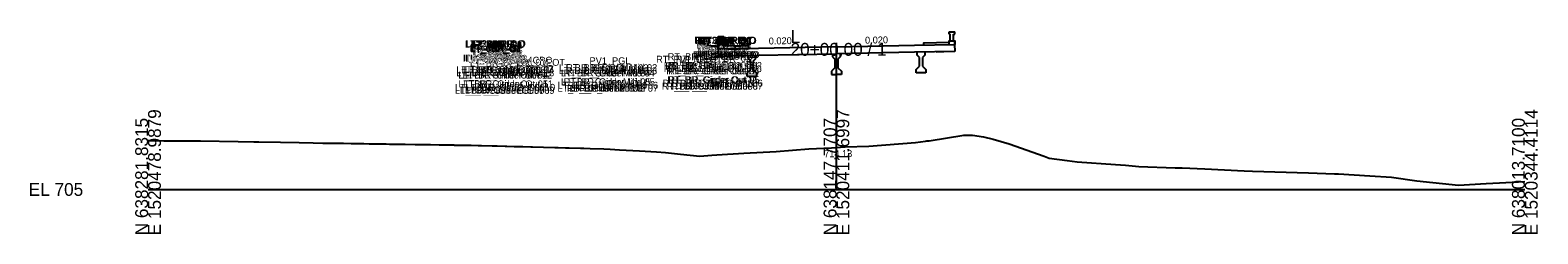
# Model space of a CAD drawing. Extents: x -26 to 3903, y -10 to 9531.
# Drawn here: x 974.3 to 1302.8, y -9.7 to 34.8 of the extents above; entities that cross this region are included whole.
import ezdxf

# ---------------------------------------------------------------- set-up
doc = ezdxf.new("R2010")
doc.units = 0
for name, color, linetype in [('Default', 7, 'Continuous'), ('Exist Cross Section Cell', 7, 'Continuous'), ('Exist XS Center Line Elevation Label', 7, 'Continuous'), ('Exist XS Ground Line', 7, 'Continuous'), ('Prop CMT Conc Surface', 7, 'Continuous'), ('Prop XS Conc Monolithic Island', 7, 'Continuous'), ('Prop XS Finish Grade', 7, 'Continuous'), ('Prop XS SE Text', 7, 'Continuous')]:
    doc.layers.add(name, color=color, linetype=linetype)

msp = doc.modelspace()

# ---------------------------------------------------------------- linework, layer by layer
at = {"layer": 'Exist Cross Section Cell'}
for p, q in [((1150, 0), (1150, 31.96)), ((1000, 0), (1150, 0)), ((1150, 0), (1300, 0))]:
    msp.add_line(p, q, dxfattribs=at)
at = {"layer": 'Exist XS Ground Line'}
msp.add_lwpolyline([(1000, 10.65), (1001.54, 10.65), (1003.43, 10.64), (1008.98, 10.64), (1011.39, 10.63), (1019.6, 10.46), (1023.06, 10.38), (1024.11, 10.36), (1028.84, 10.28), (1032.95, 10.21), (1035.98, 10.16), (1038.09, 10.13), (1038.91, 10.12), (1039.29, 10.11), (1040.73, 10.1), (1041.42, 10.09), (1042.61, 10.07), (1044.23, 10.04), (1044.45, 10.04), (1044.85, 10.03), (1046.3, 10.01), (1047.03, 10), (1048.17, 9.98), (1049.82, 9.96), (1050.46, 9.95), (1051.89, 9.92), (1052.61, 9.91), (1054.79, 9.88), (1055.41, 9.87), (1056.02, 9.86), (1058.21, 9.82), (1060.48, 9.79), (1061.01, 9.79), (1061.18, 9.78), (1061.54, 9.78), (1063.42, 9.75), (1063.8, 9.74), (1064.51, 9.74), (1065.79, 9.72), (1066.61, 9.7), (1066.77, 9.69), (1067.09, 9.69), (1068.33, 9.69), (1068.63, 9.68), (1070.37, 9.63), (1071.95, 9.59), (1072.35, 9.58), (1072.66, 9.57), (1075, 9.51), (1076.07, 9.49), (1077.8, 9.44), (1077.94, 9.44), (1078.21, 9.43), (1079.8, 9.4), (1080.59, 9.38), (1081.66, 9.35), (1083.4, 9.31), (1083.52, 9.31), (1083.77, 9.3), (1086.19, 9.24), (1088.61, 9.18), (1088.98, 9.17), (1089.1, 9.17), (1089.35, 9.16), (1090.97, 9.11), (1091.78, 9.09), (1094.22, 9.02), (1094.57, 9.01), (1094.69, 9), (1094.92, 9), (1096.37, 8.94), (1099.35, 8.87), (1100.7, 8.78), (1102.72, 8.65), (1107.06, 8.4), (1110.79, 8.18), (1112.74, 8.07), (1116.05, 7.73), (1120.24, 7.26), (1122.82, 7.5), (1123.92, 7.58), (1129.85, 7.93), (1136.85, 8.28), (1143.98, 8.85), (1148.9, 9.07), (1151.92, 9.27), (1157.06, 9.44), (1167.22, 10.27), (1169.41, 10.55), (1169.69, 10.6), (1169.85, 10.62), (1170.17, 10.62), (1177.79, 11.86), (1179.64, 11.83), (1182.08, 11.46), (1184.16, 10.99), (1187.66, 9.95), (1195.23, 7.28), (1195.97, 6.98), (1196.38, 6.84), (1200.26, 6.35), (1202.47, 6.05), (1210.8, 5.46), (1213.02, 5.3), (1215.89, 5.03), (1223.78, 4.75), (1225.37, 4.69), (1230.31, 4.48), (1238.84, 4.09), (1240.68, 4), (1252.88, 3.62), (1258.54, 3.43), (1259.39, 3.38), (1266.2, 2.98), (1270.96, 2.66), (1276.48, 1.89), (1285.57, 0.9), (1291.6, 1.29), (1294.51, 1.46), (1300, 1.76)], dxfattribs=at)
at = {"layer": 'Prop XS Conc Monolithic Island'}
for p, q in [((1124.22, 32.85), (1124.22, 33.35)), ((1124.22, 33.35), (1125.47, 33.35)), ((1125.47, 32.85), (1125.47, 33.35)), ((1174.53, 33.88), (1174.53, 34.38)), ((1174.53, 34.38), (1175.78, 34.38)), ((1174.78, 33.88), (1174.53, 33.88)), ((1174.78, 32.38), (1174.78, 33.88)), ((1175.53, 32.38), (1175.53, 33.88)), ((1175.53, 33.88), (1175.78, 33.88)), ((1175.78, 33.88), (1175.78, 34.38)), ((1124.47, 32.85), (1124.22, 32.85)), ((1124.22, 30.59), (1124.22, 31.35)), ((1124.22, 31.35), (1124.47, 31.35)), ((1124.47, 31.35), (1124.47, 32.85)), ((1125.22, 31.35), (1125.22, 32.85)), ((1125.22, 32.85), (1125.47, 32.85)), ((1125.47, 31.35), (1125.22, 31.35)), ((1125.47, 30.59), (1125.47, 31.35)), ((1174.53, 31.62), (1174.53, 32.38)), ((1174.53, 32.38), (1174.78, 32.38)), ((1175.78, 32.38), (1175.53, 32.38)), ((1175.78, 31.62), (1175.78, 32.38))]:
    msp.add_line(p, q, dxfattribs=at)
for points in [[(1150, 31.11), (1133, 30.77), (1124.22, 30.59)], [(1124.22, 30.59), (1124.25, 29.09)], [(1124.25, 29.09), (1133, 29.27), (1150, 29.61)], [(1126.29, 30.63), (1131, 30.73)], [(1149.17, 29.59), (1149.17, 28.94)], [(1150, 31.11), (1167, 31.45), (1175.78, 31.62)], [(1175.78, 30.12), (1167, 29.95), (1150, 29.61)], [(1150.83, 29.62), (1150.83, 28.94)], [(1167.59, 29.31), (1167.59, 29.96)], [(1169.26, 29.99), (1169.26, 29.31)], [(1171.75, 30.04), (1172.58, 30.06), (1173.42, 30.07)], [(1175.75, 31.65), (1175.78, 30.12)], [(1128.25, 29.17), (1127.42, 29.15), (1126.58, 29.14)], [(1130.74, 29.22), (1130.74, 28.57)], [(1130.74, 28.57), (1131.24, 28.07)], [(1131.24, 28.07), (1131.24, 26.15)], [(1131.91, 28.07), (1132.41, 28.57)], [(1131.91, 26.15), (1131.91, 28.07)], [(1132.41, 28.57), (1132.41, 29.25)], [(1149.67, 26.52), (1148.92, 25.77)], [(1149.17, 28.94), (1149.67, 28.44)], [(1149.67, 28.44), (1149.67, 26.52)], [(1150.83, 28.94), (1150.33, 28.44)], [(1150.33, 28.44), (1150.33, 26.52)], [(1150.33, 26.52), (1151.08, 25.77)], [(1167.34, 26.14), (1168.09, 26.89)], [(1168.09, 28.81), (1167.59, 29.31)], [(1168.09, 26.89), (1168.09, 28.81)], [(1169.26, 29.31), (1168.76, 28.81)], [(1168.76, 28.81), (1168.76, 26.89)], [(1168.76, 26.89), (1169.51, 26.14)], [(1131.24, 26.15), (1130.49, 25.4)], [(1130.49, 25.4), (1130.49, 24.74)], [(1130.49, 24.74), (1131.58, 24.74), (1132.66, 24.74)], [(1132.66, 25.4), (1131.91, 26.15)], [(1132.66, 24.74), (1132.66, 25.4)], [(1148.92, 25.77), (1148.92, 25.11)], [(1148.92, 25.11), (1150, 25.11)], [(1151.08, 25.11), (1150, 25.11)], [(1151.08, 25.77), (1151.08, 25.11)], [(1167.34, 25.47), (1167.34, 26.14)], [(1169.51, 25.47), (1168.42, 25.47), (1167.34, 25.47)], [(1169.51, 26.14), (1169.51, 25.47)]]:
    msp.add_lwpolyline(points, dxfattribs=at)
at = {"layer": 'Prop XS Finish Grade'}
for p, q in [((1130.93, 30.72), (1130.93, 31.28)), ((1169.07, 31.49), (1169.07, 31.99))]:
    msp.add_line(p, q, dxfattribs=at)
for points in [[(1130.93, 30.72), (1130.93, 31.28), (1125.43, 31.33), (1125.43, 31.68), (1124.22, 31.68), (1124.22, 30.59)], [(1169.07, 31.49), (1169.07, 31.99), (1174.57, 32.1), (1174.57, 32.44), (1175.78, 32.44), (1175.78, 31.62)]]:
    msp.add_lwpolyline(points, dxfattribs=at)

# ---------------------------------------------------------------- texts
at = {"layer": 'Default'}
msp.add_text('-', height=0.0001, dxfattribs=at).set_placement((1000, 0))
at = {"layer": 'Exist Cross Section Cell'}
for s, p in [('L', (1140, 31.96)), ('20+00.00 / 1', (1140, 29.16)), ('EL 705', (974, -1.4))]:
    msp.add_text(s, height=2.8, dxfattribs=at).set_placement(p)
for s, p in [('E 1520478.9879', (1002.8, -10)), ('E 1520411.6997', (1152.8, -10)), ('E 1520344.4114', (1302.8, -10)), ('N 638281.8315', (1000, -10)), ('N 638147.7707', (1150, -10)), ('N 638013.7100', (1300, -10))]:
    msp.add_text(s, height=2.8, rotation=90, dxfattribs=at).set_placement(p)
at = {"layer": 'Exist XS Center Line Elevation Label'}
msp.add_text('714.13', height=1.5, rotation=0.8401, dxfattribs=at).set_placement((1147.32, 7.01))
at = {"layer": 'Prop CMT Conc Surface'}
for s, p in [('RT_2BMRP_O', (1119.01, 31.81)), ('RT_3BMRP_O', (1119.15, 31.81)), ('RT_5BMRP_O', (1119.24, 31.72)), ('RT_4BR_O1', (1119.66, 31.64)), ('RT_3BR_O1', (1119.74, 31.74)), ('RT_2BR_O1', (1119.97, 31.81)), ('RT_6BR_O1', (1119.97, 31.47)), ('RT_0BR_O1', (1120.05, 31.64)), ('RT_5BR_O', (1120.06, 31.54)), ('RT_1BR_O1', (1120.23, 31.81)), ('RT_7BR_O', (1120.38, 31.47)), ('LT_5BMRP_O', (1069.03, 30.96)), ('LT_3BMRP_O', (1069.11, 31.05)), ('LT_2BMRP_O', (1069.26, 31.05)), ('LT_0BR_O2', (1070.09, 30.05)), ('LT_2BR_O2', (1070.17, 30.21)), ('LT_6BR_O2', (1070.17, 29.88)), ('LT_1BR_O2', (1070.27, 30.21)), ('LT_0BR_O1', (1070.31, 30.88)), ('LT_7BR_O1', (1070.31, 29.88)), ('LT_2BR_O1', (1070.39, 31.05)), ('LT_6BR_O1', (1070.39, 30.71)), ('LT_3BR_O2', (1070.4, 30.15)), ('LT_5BR_O2', (1070.4, 29.94)), ('LT_1BR_O1', (1070.49, 31.05)), ('LT_4BR_O2', (1070.49, 30.05)), ('LT_3BR_O1', (1070.62, 30.98)), ('LT_7BR_O', (1070.63, 30.71)), ('LT_0BR_O', (1070.63, 28.89)), ('LT_6BR_O', (1070.63, 28.64)), ('LT_5BR_O1', (1070.64, 28.4)), ('LT_4BR_O1', (1070.7, 30.88)), ('LT_1BR_O', (1070.81, 29.14)), ('LT_5BR_O', (1070.94, 30.78)), ('LT_2BR_O', (1070.96, 29.38)), ('LT_3BR_O', (1071.05, 29.39)), ('LT_4BR_O', (1071.05, 28.39)), ('RT_BR_4CPO', (1113.23, 28.2)), ('RT_BR_2CPO', (1118.73, 28.65)), ('RT_BR_3CPO', (1118.73, 28.31)), ('RT_4BMRP_O', (1119.15, 28.65)), ('RT_1BMRP_O', (1119.19, 28.65)), ('RT_4BR_O2', (1119.44, 30.81)), ('RT_3BR_O2', (1119.52, 30.91)), ('RT_5BR_O2', (1119.52, 30.7)), ('RT_6BMRP_O', (1119.63, 28.65)), ('RT_5BR_O1', (1119.73, 29.16)), ('RT_2BR_O2', (1119.75, 30.97)), ('RT_6BR_O2', (1119.75, 30.64)), ('RT_0BR_O2', (1119.84, 30.81)), ('RT_3BR_O', (1119.96, 30.15)), ('RT_4BR_O', (1119.96, 29.15)), ('RT_1BR_O2', (1120.02, 30.97)), ('RT_2BR_O', (1120.05, 30.14)), ('RT_7BR_O1', (1120.05, 30.64)), ('RT_BR_1CPO', (1120.12, 28.65)), ('RT_0BR_O', (1120.38, 29.65)), ('RT_6BR_O', (1120.38, 29.4)), ('RT_1BR_O', (1120.56, 29.9)), ('LT_BR_Girder Out 02', (1067.17, 25.35)), ('LT_BR_Girder Out 01', (1068.22, 25.36)), ('LT_6BMRP_O', (1068.63, 27.89)), ('LT_BR_1CPO', (1068.79, 27.89)), ('LT_BR_Girder Out 14', (1068.97, 25.38)), ('LT_4BMRP_O', (1069.11, 27.89)), ('LT_1BMRP_O', (1069.44, 27.89)), ('LT_BR_2CPO', (1069.82, 27.89)), ('LT_BR_3CPO', (1069.82, 27.55)), ('LT_BR_06', (1070.11, 25.3)), ('LT_BR_02', (1070.15, 26.8)), ('LT_BR_4CPO', (1075.32, 27.44)), ('LT_PV1_OEOT', (1076.8, 26.98)), ('LT_BR_01', (1077.07, 26.94)), ('LT_BR_07', (1078.79, 25.48)), ('LT_BR_Girder Mid 03', (1089.5, 25.15)), ('LT_BR_Girder Mid 02', (1089.53, 25.8)), ('RT_BR_Girder Mid 03', (1091.08, 25.15)), ('RT_BR_Girder Mid 02', (1091.11, 25.83)), ('PV1_PGL', (1096.2, 27.32)), ('BR_PGL', (1096.63, 25.82)), ('RT_PV1_OEOT', (1110.71, 27.66)), ('RT_BR_Girder Out 14', (1112.38, 26.25)), ('RT_BR_Girder Out 13', (1112.4, 25.6)), ('RT_BR_07', (1112.7, 26.16)), ('RT_BR_Girder Out 12', (1112.93, 25.1)), ('RT_BR_Girder Out 01', (1113.3, 26.27)), ('RT_BR_Girder Out 04', (1113.37, 25.1)), ('RT_BR_Girder Out 03', (1113.89, 25.6)), ('RT_BR_Girder Out 02', (1113.92, 26.28)), ('RT_BR_01', (1114.99, 27.7)), ('RT_BR_06', (1121.43, 26.33)), ('RT_BR_02', (1121.48, 27.83)), ('LT_BR_Girder Out 06', (1066.88, 21.53)), ('LT_BR_Girder Out 03', (1067.15, 24.7)), ('LT_BR_Girder Out 04', (1067.62, 24.2)), ('LT_BR_Girder Out 05', (1067.64, 22.28)), ('LT_BR_Girder Out 12', (1068.52, 24.2)), ('LT_BR_Girder Out 11', (1068.74, 22.28)), ('LT_BR_Girder Out 13', (1068.99, 24.7)), ('LT_BR_Girder Out 10', (1069.21, 21.53)), ('LT_BR_Girder Mid 06', (1089.24, 21.98)), ('LT_BR_Girder Mid 04', (1089.98, 24.65)), ('LT_BR_Girder Mid 05', (1089.99, 22.73)), ('RT_BR_Girder Mid 04', (1090.56, 24.65)), ('RT_BR_Girder Mid 05', (1090.57, 22.73)), ('RT_BR_Girder Mid 06', (1091.31, 21.98)), ('RT_BR_Girder Out 09', (1111.96, 21.77)), ('RT_BR_Girder Out 10', (1112.12, 22.43)), ('RT_BR_Girder Out 08', (1113.04, 21.77)), ('RT_BR_Girder Out 11', (1113.15, 23.18)), ('RT_BR_Girder Out 05', (1113.38, 23.18)), ('RT_BR_Girder Out 07', (1114.1, 21.77)), ('RT_BR_Girder Out 06', (1114.12, 22.43)), ('LT_BR_Girder Out 07', (1066.86, 20.86)), ('LT_BR_Girder Out 08', (1067.96, 20.86)), ('LT_BR_Girder Out 09', (1069.05, 20.86)), ('LT_BR_Girder Mid 07', (1089.21, 21.32)), ('RT_BR_Girder Mid 07', (1091.29, 21.32)), ('BR_Girder Mid 08', (1091.77, 21.32))]:
    msp.add_text(s, height=1.5, dxfattribs=at).set_placement(p)
at = {"layer": 'Prop XS SE Text'}
for p in [(1135.26, 31.62), (1156.24, 31.8)]:
    msp.add_text('0.020', height=1.5, rotation=1.1458, dxfattribs=at).set_placement(p)

doc.saveas('drawing.dxf')
